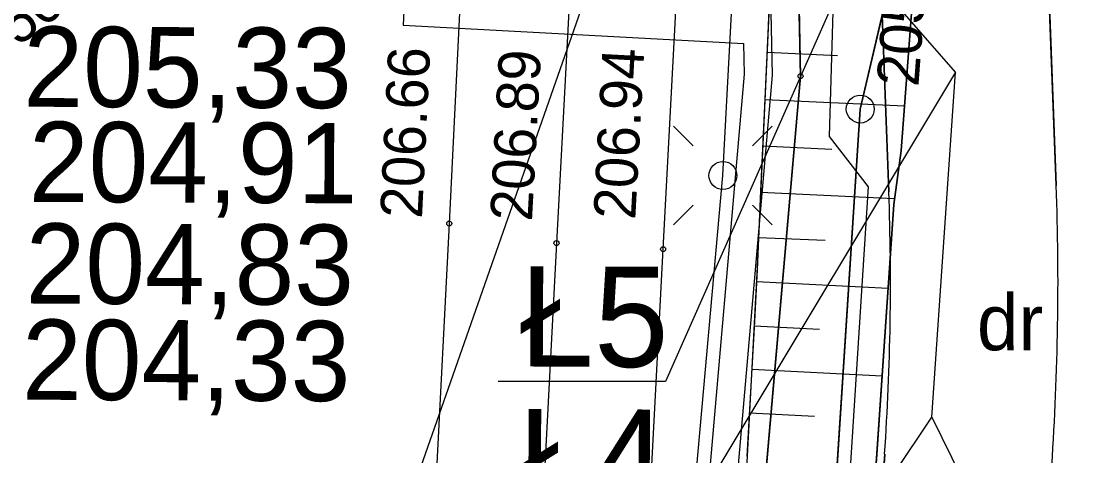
# Model space of a CAD drawing. Extents: x 6512606 to 6513006, y 6022524 to 6022728.
# Drawn here: x 6512717.27 to 6512736.18, y 6022641.08 to 6022648.87 of the extents above; entities that cross this region are included whole.
import ezdxf

# ---------------------------------------------------------------- set-up
doc = ezdxf.new("R2010")
doc.units = 0
for name, color, linetype in [('000 Inne (niezydentyfikowane)', 7, 'Continuous'), ('20', 7, 'Continuous'), ('202-punkt graniczny', 7, 'Continuous'), ('203-punkt graniczny', 7, 'Continuous'), ('210-oznaczenie konturu użytku gruntowego', 7, 'Continuous'), ('218-kontur użytku gruntowego', 7, 'Continuous'), ('219-działka ewidencyjna', 7, 'Continuous'), ('4', 7, 'Continuous'), ('chodnik (powierzchnia)', 7, 'Continuous'), ('Default', 7, 'Continuous'), ('E_OSW_KABLE', 7, 'Continuous'), ('jezdnia (powierzchnia)', 7, 'Continuous'), ('kolor_kostka_bet', 7, 'Continuous'), ('kolor_sc_rowerowa', 7, 'Continuous'), ('krawężnik (linia)', 7, 'Continuous'), ('latarnia (punkt)', 7, 'Continuous'), ('Level 47', 7, 'Continuous'), ('maxp_kan_deszczowa', 7, 'Continuous'), ('maxp_krawężnik', 7, 'Continuous'), ('maxp_obrzeże', 7, 'Continuous'), ('maxp_ramka_2', 7, 'Continuous'), ('przewód elektroenergetyczny (linia)', 7, 'Continuous'), ('punkt wysokościowy sztuczny', 7, 'Continuous'), ('punkt wysokościowy sztuczny-Atr2', 7, 'Continuous'), ('skarpa nieumocniona (powierzchnia)', 7, 'Continuous')]:
    doc.layers.add(name, color=color, linetype=linetype)

# ---------------------------------------------------------------- blocks, each defined once
blk = doc.blocks.new('203')
at = {"layer": 'Default'}
blk.add_circle((0, 0), 0.45, dxfattribs=at)
blk = doc.blocks.new('202')
at = {"layer": 'Default'}
blk.add_circle((0, 0), 2.5, dxfattribs=at)
blk = doc.blocks.new('PW02')
at = {"layer": 'Default'}
blk.add_circle((0, 0), 0.45, dxfattribs=at)
blk = doc.blocks.new('SM01')
at = {"layer": 'Default'}
for p, q in [((-5.3, 5.31), (-8.83, 8.84)), ((5.31, 5.31), (8.84, 8.84)), ((-5.3, -5.3), (-8.83, -8.83)), ((5.31, -5.3), (8.84, -8.83))]:
    blk.add_line(p, q, dxfattribs=at)
blk.add_circle((0, 0), 2.5, dxfattribs=at)

msp = doc.modelspace()

# ---------------------------------------------------------------- linework, layer by layer
at = {"layer": '000 Inne (niezydentyfikowane)'}
for points in [[(6512730.63, 6022648.31), (6512731.89, 6022648.25)], [(6512730.59, 6022647.46), (6512733.09, 6022647.35)], [(6512730.55, 6022646.63), (6512731.79, 6022646.57)], [(6512730.52, 6022645.8), (6512732.91, 6022645.69)], [(6512730.48, 6022644.99), (6512731.67, 6022644.94)], [(6512730.44, 6022644.2), (6512732.8, 6022644.08)], [(6512730.4, 6022643.41), (6512731.57, 6022643.35)], [(6512730.36, 6022642.63), (6512732.69, 6022642.51)], [(6512730.32, 6022641.85), (6512731.48, 6022641.79)]]:
    msp.add_lwpolyline(points, dxfattribs=at)
at = {"layer": '20'}
for p, q in [((6512727.742, 6022650.343), (6512723.33, 6022637.748)), ((6512732.187, 6022650.039), (6512728.812, 6022642.41)), ((6512734.006, 6022647.952), (6512729.141, 6022639.852)), ((6512728.812, 6022642.41), (6512725.816, 6022642.41))]:
    msp.add_line(p, q, dxfattribs=at)
at = {"layer": '218-kontur użytku gruntowego'}
for points in [[(6512731.23, 6022647.88), (6512730.8, 6022668.08)], [(6512730.8, 6022668.08), (6512731.23, 6022647.88)], [(6512733.08, 6022650.62), (6512732.3, 6022647.29)], [(6512732.3, 6022647.29), (6512733.08, 6022650.62)], [(6512729.5, 6022628.07), (6512731.23, 6022647.88)], [(6512731.23, 6022647.88), (6512729.5, 6022628.07)], [(6512732.3, 6022647.29), (6512731.57, 6022636.01)], [(6512731.57, 6022636.01), (6512732.3, 6022647.29)]]:
    msp.add_lwpolyline(points, dxfattribs=at)
at = {"layer": '219-działka ewidencyjna'}
for points in [[(6512730.8, 6022668.08), (6512731.23, 6022647.88)], [(6512732.3, 6022647.29), (6512736.07, 6022663.44)], [(6512727.91, 6022609.85), (6512731.23, 6022647.88)], [(6512728.87, 6022594.38), (6512732.3, 6022647.29)]]:
    msp.add_lwpolyline(points, dxfattribs=at)
at = {"layer": '4'}
for points in [[(6512730.8, 6022668.08), (6512731.23, 6022647.88)], [(6512732.3, 6022647.29), (6512736.07, 6022663.44)], [(6512727.91, 6022609.85), (6512731.23, 6022647.88)], [(6512728.87, 6022594.38), (6512732.3, 6022647.29)]]:
    msp.add_lwpolyline(points, dxfattribs=at)
at = {"layer": 'chodnik (powierzchnia)'}
msp.add_lwpolyline([(6512729.71, 6022662.42), (6512727.8, 6022662.54), (6512726.86, 6022644.89), (6512726.27, 6022633.62), (6512728.18, 6022633.51), (6512728.77, 6022644.78)], close=True, dxfattribs=at)
at = {"layer": 'E_OSW_KABLE'}
msp.add_lwpolyline([(6512724.836, 6022600.607), (6512729.94, 6022610.367), (6512731.171, 6022625.931), (6512732.446, 6022645.898), (6512731.748, 6022646.801), (6512731.905, 6022652.094)], dxfattribs=at)
at = {"layer": 'jezdnia (powierzchnia)'}
msp.add_lwpolyline([(6512731.22, 6022666.45), (6512731.29, 6022656.48), (6512731.47, 6022656.36), (6512731.64, 6022656.23), (6512731.8, 6022656.1), (6512731.95, 6022655.95), (6512732.1, 6022655.8), (6512732.24, 6022655.64), (6512732.37, 6022655.47), (6512732.49, 6022655.3), (6512732.61, 6022655.12), (6512732.71, 6022654.94), (6512732.81, 6022654.75), (6512732.89, 6022654.55), (6512732.97, 6022654.35), (6512733.03, 6022654.15), (6512733.34, 6022650.68), (6512733.03, 6022646.55), (6512732.9, 6022645.58), (6512731.83, 6022629.89)], dxfattribs=at)
at = {"layer": 'kolor_kostka_bet'}
for p, q in [((6512735.602, 6022651.319), (6512735.81, 6022645.921)), ((6512732.812, 6022645.812), (6512732.605, 6022651.204)), ((6512731.23, 6022647.88), (6512727.91, 6022609.85))]:
    msp.add_line(p, q, dxfattribs=at)
for points in [[(6512708.915, 6022572.782), (6512706.28, 6022574.16), (6512716.29, 6022587.65), (6512727.91, 6022609.85), (6512731.23, 6022647.88), (6512731.197, 6022649.415), (6512729.023, 6022649.531)], [(6512729.023, 6022649.531), (6512731.197, 6022649.415), (6512731.23, 6022647.88), (6512727.91, 6022609.85), (6512716.29, 6022587.65), (6512706.28, 6022574.16), (6512708.915, 6022572.782)], [(6512731.23, 6022647.88), (6512731.197, 6022649.415), (6512729.023, 6022649.531)], [(6512730.868, 6022613.8), (6512731.092, 6022617.073), (6512731.343, 6022620.743), (6512732.737, 6022641.11)]]:
    msp.add_lwpolyline(points, dxfattribs=at)
for radius, start in [(45, 356.0865), (48, 356.0866)]:
    msp.add_arc((6512687.841, 6022644.182), radius, start, 2.076, dxfattribs=at)
at = {"layer": 'kolor_sc_rowerowa'}
for points in [[(6512735.81, 6022645.921), (6512735.599, 6022651.415)], [(6512732.605, 6022651.204), (6512732.812, 6022645.812)], [(6512732.737, 6022641.11), (6512731.343, 6022620.743), (6512731.092, 6022617.073), (6512730.868, 6022613.8)]]:
    msp.add_lwpolyline(points, dxfattribs=at)
for radius, start in [(45, 356.0865), (48, 356.0866)]:
    msp.add_arc((6512687.841, 6022644.182), radius, start, 2.076, dxfattribs=at)
at = {"layer": 'krawężnik (linia)'}
for points in [[(6512702.473, 6022669.202), (6512710.9, 6022668.72), (6512710.75, 6022664.74), (6512710.88, 6022663.85), (6512711.57, 6022663.54), (6512725.79, 6022662.66), (6512724.94, 6022645.24), (6512724.45, 6022635.71), (6512706.43, 6022636.73), (6512701.814, 6022636.999)], [(6512731.83, 6022629.89), (6512732.9, 6022645.58), (6512733.03, 6022646.55), (6512733.34, 6022650.68), (6512733.03, 6022654.15), (6512732.97, 6022654.35), (6512732.89, 6022654.55), (6512732.81, 6022654.75), (6512732.71, 6022654.94), (6512732.61, 6022655.12), (6512732.49, 6022655.3), (6512732.37, 6022655.47), (6512732.24, 6022655.64), (6512732.1, 6022655.8), (6512731.95, 6022655.95), (6512731.8, 6022656.1), (6512731.64, 6022656.23), (6512731.47, 6022656.36), (6512731.29, 6022656.48), (6512731.22, 6022666.45)]]:
    msp.add_lwpolyline(points, dxfattribs=at)
at = {"layer": 'maxp_kan_deszczowa'}
msp.add_line((6512733.583, 6022641.769), (6512734.006, 6022647.952), dxfattribs=at)
for points in [[(6512741.065, 6022638.988), (6512741.55, 6022649.49), (6512730.76, 6022651.147), (6512730.76, 6022651.147), (6512730.665, 6022649.115), (6512730.652, 6022648.777), (6512730.588, 6022647.474), (6512730.511, 6022645.827), (6512730.451, 6022644.413), (6512730.397, 6022643.379), (6512730.27, 6022641.07)], [(6512734.006, 6022647.952), (6512732.187, 6022650.039), (6512732.187, 6022650.039), (6512728.24, 6022650.309)]]:
    msp.add_lwpolyline(points, dxfattribs=at)
msp.add_lwpolyline([(6512732.907, 6022640.763), (6512733.583, 6022641.769), (6512734.116, 6022640.68)], close=True, dxfattribs=at)
at = {"layer": 'maxp_krawężnik'}
msp.add_line((6512735.599, 6022651.415), (6512735.81, 6022645.921), dxfattribs=at)
msp.add_arc((6512687.841, 6022644.182), 48, 356.0865, 2.076, dxfattribs=at)
at = {"layer": 'maxp_obrzeże'}
for p, q in [((6512732.605, 6022651.204), (6512732.812, 6022645.805)), ((6512730.868, 6022613.8), (6512732.737, 6022641.111))]:
    msp.add_line(p, q, dxfattribs=at)
msp.add_arc((6512687.841, 6022644.182), 45, 356.0865, 2.076, dxfattribs=at)
at = {"layer": 'maxp_ramka_2'}
for p, q in [((6512724.95, 6022665.965), (6512724.112, 6022648.791)), ((6512724.112, 6022648.791), (6512730.217, 6022648.466))]:
    msp.add_line(p, q, dxfattribs=at)
for points in [[(6512721.086, 6022597.89), (6512727.421, 6022609.993), (6512730.73, 6022647.896), (6512730.304, 6022667.864), (6512724.475, 6022673.519)], [(6512729.218, 6022636.335), (6512730.229, 6022647.913), (6512730.217, 6022648.466)]]:
    msp.add_lwpolyline(points, dxfattribs=at)
at = {"layer": 'przewód elektroenergetyczny (linia)'}
msp.add_lwpolyline([(6512701.756, 6022634.173), (6512720.37, 6022633.07), (6512728.65, 6022632.8), (6512729.84, 6022646.1), (6512731.03, 6022668.44), (6512718.53, 6022669.06), (6512712.43, 6022669.64), (6512702.495, 6022670.296)], dxfattribs=at)
at = {"layer": 'skarpa nieumocniona (powierzchnia)'}
msp.add_lwpolyline([(6512730.46, 6022644.58), (6512730.06, 6022637.01), (6512732.31, 6022636.92), (6512732.9, 6022645.58), (6512733.03, 6022646.55), (6512733.34, 6022650.68), (6512733.03, 6022654.15), (6512732.81, 6022654.75), (6512732.24, 6022655.64), (6512731.8, 6022656.1), (6512731.39, 6022656.42), (6512730.87, 6022653.56)], close=True, dxfattribs=at)
msp.add_lwpolyline([(6512730.46, 6022644.58), (6512730.06, 6022637.01), (6512732.31, 6022636.92), (6512732.9, 6022645.58), (6512733.03, 6022646.55), (6512733.34, 6022650.68), (6512733.03, 6022654.15), (6512732.81, 6022654.75), (6512732.24, 6022655.64), (6512731.8, 6022656.1), (6512731.39, 6022656.42), (6512730.87, 6022653.56)], close=True, dxfattribs=at)

# ---------------------------------------------------------------- block references
at = {"layer": '202-punkt graniczny', "xscale": 0.1, "yscale": 0.10000000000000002}
msp.add_blockref('202', (6512732.3, 6022647.29), dxfattribs=at)
at = {"layer": '203-punkt graniczny', "xscale": 0.1, "yscale": 0.10000000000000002}
msp.add_blockref('203', (6512731.23, 6022647.88), dxfattribs=at)
at = {"layer": 'latarnia (punkt)', "xscale": 0.1, "yscale": 0.10000000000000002}
msp.add_blockref('SM01', (6512729.84, 6022646.1), dxfattribs=at)
at = {"layer": 'punkt wysokościowy sztuczny', "xscale": 0.1, "yscale": 0.10000000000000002}
for p in [(6512724.94, 6022645.24), (6512726.86, 6022644.89), (6512728.77, 6022644.78)]:
    msp.add_blockref('PW02', p, dxfattribs=at)

# ---------------------------------------------------------------- texts
at = {"layer": '210-oznaczenie konturu użytku gruntowego'}
msp.add_text('dr', height=1, dxfattribs=at).set_placement((6512734.39, 6022642.97))
at = {"layer": 'Level 47'}
for s, height, p in [('205,33', 1.4377, (6512717.311, 6022647.333)), ('204,91', 1.4377, (6512717.409, 6022645.629)), ('204,83', 1.4377, (6512717.35, 6022643.808)), ('Ł5', 1.7971, (6512726.193, 6022642.68)), ('204,33', 1.4377, (6512717.286, 6022642.085)), ('Ł4', 1.7971, (6512726.157, 6022640.122))]:
    msp.add_text(s, height=height, rotation=359.7281, dxfattribs=at).set_placement(p)
at = {"layer": 'punkt wysokościowy sztuczny-Atr2'}
for s, rotation, p in [('205.78', 85.707, (6512733.34, 6022647.68)), ('206.50', 37.212, (6512715.66, 6022647.22)), ('206.66', 87.206, (6512724.45, 6022645.32)), ('206.89', 86.951, (6512726.42, 6022645.27)), ('206.94', 86.949, (6512728.27, 6022645.3))]:
    msp.add_text(s, height=0.75, rotation=rotation, dxfattribs=at).set_placement(p)

doc.saveas('drawing.dxf')
